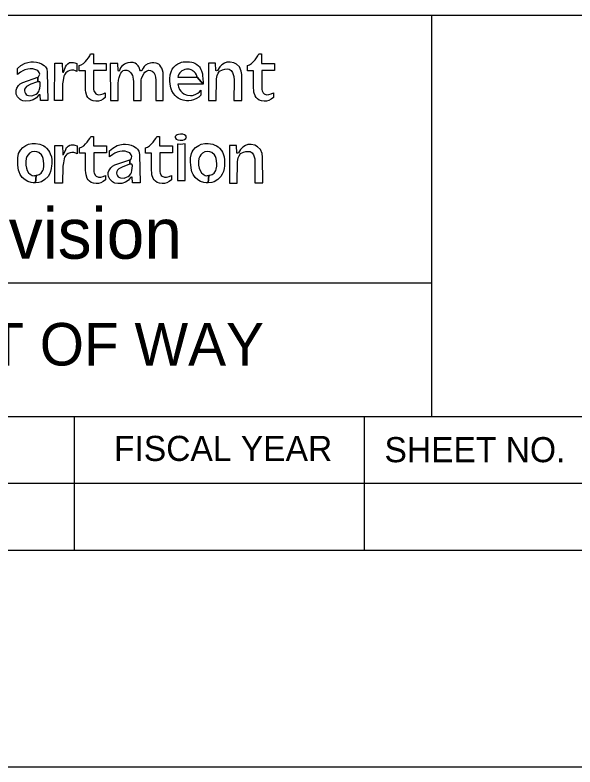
# Model space of a CAD drawing. Extents: x -507127 to -501139, y -509578 to -506434.
# Drawn here: x -504651.4 to -504486.7, y -508267.1 to -508046 of the extents above; entities that cross this region are included whole.
import ezdxf

# ---------------------------------------------------------------- set-up
doc = ezdxf.new("R2010")
doc.units = 0
doc.layers.add('rowdsnConstructCell', color=7, linetype='Continuous')

msp = doc.modelspace()

# ---------------------------------------------------------------- linework, layer by layer
at = {"layer": 'rowdsnConstructCell'}
for p, q in [((-504971.83, -508045.97), (-504397.68, -508045.97)), ((-504528.91, -508045.97), (-504528.91, -508164.08)), ((-504840.59, -508124.71), (-504528.91, -508124.71)), ((-507022.35, -508164.08), (-504397.68, -508164.08)), ((-505381.93, -508164.08), (-504397.68, -508164.08)), ((-504633.9, -508203.46), (-504633.9, -508164.09)), ((-504548.6, -508203.46), (-504548.6, -508164.09)), ((-504397.68, -508183.77), (-504794.66, -508183.77)), ((-504397.68, -508203.45), (-507022.35, -508203.45)), ((-507126.68, -508267.1), (-504293.35, -508267.1))]:
    msp.add_line(p, q, dxfattribs=at)
for points in [[(-504632.5, -508060.84), (-504631.89, -508060.59), (-504631.25, -508060.2), (-504630.69, -508059.66), (-504630.22, -508059.14), (-504629.78, -508058.53), (-504629.41, -508058.01), (-504629.14, -508057.42), (-504628.33, -508057.42), (-504628.33, -508060.18), (-504624.55, -508060.18), (-504624.55, -508062.3), (-504628.28, -508062.3), (-504628.27, -508067.9), (-504628.17, -508068.22), (-504627.79, -508068.89), (-504627.79, -508068.89), (-504627.58, -508069.12), (-504626.89, -508069.42), (-504626.22, -508069.39), (-504625.49, -508069.18), (-504624.82, -508068.89), (-504624.82, -508070.24), (-504625.47, -508070.69), (-504626.17, -508071.07), (-504626.87, -508071.26), (-504627.19, -508071.28), (-504627.59, -508071.29), (-504628.37, -508071.16), (-504629.01, -508070.97), (-504629.55, -508070.58), (-504629.93, -508070.21), (-504630.21, -508069.78), (-504630.56, -508068.69), (-504630.63, -508068.03), (-504630.68, -508067.49), (-504630.68, -508062.35), (-504632.5, -508062.35)], [(-504583.04, -508060.84), (-504582.43, -508060.59), (-504581.8, -508060.2), (-504581.24, -508059.66), (-504580.77, -508059.14), (-504580.33, -508058.53), (-504579.95, -508058.01), (-504579.69, -508057.42), (-504578.88, -508057.42), (-504578.88, -508060.18), (-504575.1, -508060.18), (-504575.1, -508062.3), (-504578.83, -508062.3), (-504578.81, -508067.9), (-504578.72, -508068.22), (-504578.35, -508068.89), (-504578.35, -508068.89), (-504578.13, -508069.12), (-504577.44, -508069.42), (-504576.77, -508069.39), (-504576.04, -508069.18), (-504575.37, -508068.89), (-504575.37, -508070.24), (-504576.02, -508070.69), (-504576.71, -508071.07), (-504577.41, -508071.26), (-504577.74, -508071.28), (-504578.14, -508071.29), (-504578.92, -508071.16), (-504579.56, -508070.97), (-504580.1, -508070.58), (-504580.48, -508070.21), (-504580.76, -508069.78), (-504581.11, -508068.69), (-504581.17, -508068.03), (-504581.23, -508067.49), (-504581.23, -508062.35), (-504583.04, -508062.35)], [(-504650.66, -508063.46), (-504650.66, -508061.72), (-504649.7, -508060.86), (-504648.41, -508060.14), (-504647.6, -508059.91), (-504646.71, -508059.74), (-504645.98, -508059.72), (-504645.06, -508059.86), (-504644.32, -508060.01), (-504643.6, -508060.29), (-504643.6, -508060.29), (-504642.84, -508060.77), (-504642.44, -508061.23), (-504642.06, -508061.79), (-504641.89, -508062.75), (-504641.68, -508071.13), (-504643.93, -508071.13), (-504644, -508069.45), (-504644.24, -508069.42), (-504644.46, -508069.54), (-504645.08, -508070.28), (-504645.52, -508070.59), (-504646, -508070.89), (-504647.01, -508071.24), (-504648.22, -508071.32), (-504649.08, -508071.19), (-504649.53, -508070.99), (-504649.84, -508070.8), (-504650.43, -508070.24), (-504650.61, -508070.02), (-504650.99, -508069.23), (-504651.06, -508068.61), (-504651.05, -508068.08), (-504650.84, -508067.52), (-504650.34, -508066.7), (-504649.83, -508066.22), (-504649.1, -508065.82), (-504644.7, -508064.29), (-504644.7, -508065.64), (-504645.03, -508065.71), (-504646.72, -508066.35), (-504647.98, -508066.99), (-504648.34, -508067.35), (-504648.55, -508067.8), (-504648.59, -508068.29), (-504648.5, -508068.66), (-504648.31, -508069.09), (-504648.09, -508069.3), (-504647.78, -508069.51), (-504647.43, -508069.64), (-504646.42, -508069.7), (-504645.64, -508069.46), (-504645.17, -508069.23), (-504644.78, -508068.92), (-504644.42, -508068.49), (-504644.25, -508068.1), (-504644.1, -508067.49), (-504643.99, -508066.79), (-504643.95, -508066.11), (-504643.98, -508065.77), (-504644.06, -508065.66), (-504644.17, -508065.58), (-504644.51, -508065.62), (-504644.7, -508065.64), (-504644.7, -508064.29), (-504644.45, -508064.18), (-504644.23, -508063.74), (-504644.12, -508063.35), (-504644.26, -508062.83), (-504644.69, -508062.3), (-504645.56, -508061.96), (-504646.1, -508061.81), (-504646.92, -508061.77), (-504647.61, -508061.89), (-504648.47, -508062.1), (-504649.08, -508062.4), (-504649.73, -508062.8)], [(-504639.7, -508060.12), (-504637.47, -508060.12), (-504637.42, -508062.68), (-504637.35, -508062.82), (-504637.15, -508062.77), (-504637.06, -508062.55), (-504636.54, -508061.25), (-504636.27, -508060.73), (-504636.06, -508060.48), (-504635.83, -508060.29), (-504635.33, -508059.97), (-504634.98, -508059.92), (-504634.61, -508059.92), (-504634.16, -508059.96), (-504633.81, -508060.05), (-504633.17, -508060.22), (-504633.17, -508062.57), (-504633.59, -508062.39), (-504634.1, -508062.2), (-504634.39, -508062.16), (-504634.72, -508062.17), (-504635.26, -508062.31), (-504635.79, -508062.5), (-504636.16, -508062.74), (-504636.44, -508063), (-504636.86, -508063.57), (-504637.01, -508063.99), (-504637.23, -508065.19), (-504637.37, -508066.2), (-504637.46, -508071.14), (-504639.72, -508071.14)], [(-504621.03, -508071.11), (-504621.03, -508066.1), (-504620.9, -508065.08), (-504620.73, -508064.39), (-504620.43, -508063.47), (-504620.26, -508063.07), (-504620.01, -508062.66), (-504619.55, -508062.33), (-504619.16, -508062.23), (-504618.48, -508062.19), (-504618.2, -508062.24), (-504617.8, -508062.5), (-504617.44, -508062.83), (-504617.44, -508062.83), (-504617.15, -508063.24), (-504616.86, -508063.71), (-504616.75, -508064.12), (-504616.75, -508064.12), (-504616.63, -508064.93), (-504616.57, -508065.42), (-504616.56, -508071.12), (-504614.3, -508071.13), (-504614.3, -508065.01), (-504614.21, -508064.63), (-504614.01, -508064.17), (-504613.44, -508063.09), (-504613.15, -508062.73), (-504612.73, -508062.44), (-504612.15, -508062.22), (-504611.53, -508062.28), (-504611.01, -508062.5), (-504611.01, -508062.5), (-504610.57, -508062.91), (-504610.27, -508063.44), (-504610.09, -508064.28), (-504610.01, -508065.17), (-504609.97, -508066.25), (-504609.93, -508071.14), (-504607.84, -508071.14), (-504607.84, -508062.91), (-504608, -508062.14), (-504608.23, -508061.59), (-504608.45, -508061.23), (-504608.78, -508060.76), (-504609.09, -508060.47), (-504609.85, -508060.16), (-504610.55, -508060.02), (-504611.16, -508060.06), (-504611.66, -508060.12), (-504612.32, -508060.31), (-504612.97, -508060.68), (-504613.37, -508061.06), (-504613.71, -508061.59), (-504614.09, -508062.25), (-504614.27, -508062.4), (-504614.47, -508062.37), (-504614.63, -508062.12), (-504614.74, -508061.58), (-504614.94, -508061.2), (-504615.19, -508060.89), (-504615.61, -508060.39), (-504616.07, -508060.14), (-504616.66, -508059.98), (-504617.43, -508059.89), (-504618.24, -508060.01), (-504618.78, -508060.22), (-504619.22, -508060.42), (-504620.07, -508061.15), (-504620.32, -508061.48), (-504620.55, -508061.95), (-504620.75, -508062.46), (-504620.97, -508062.46), (-504621.01, -508062.27), (-504621.15, -508060.18), (-504623.35, -508060.18), (-504623.34, -508071.11)], [(-504603.54, -508066.26), (-504603.34, -508067.12), (-504602.98, -508067.87), (-504602.62, -508068.34), (-504602.2, -508068.76), (-504601.71, -508069.11), (-504601.06, -508069.41), (-504600.61, -508069.55), (-504599.78, -508069.64), (-504599.19, -508069.59), (-504598.38, -508069.38), (-504597.65, -508068.99), (-504597.09, -508068.54), (-504596.72, -508068.11), (-504596.72, -508069.58), (-504597.31, -508070.1), (-504598, -508070.55), (-504598.84, -508070.93), (-504599.59, -508071.12), (-504600.28, -508071.2), (-504600.99, -508071.19), (-504601.96, -508071.01), (-504602.58, -508070.79), (-504603.37, -508070.38), (-504603.84, -508070.03), (-504604.3, -508069.61), (-504604.75, -508069.08), (-504605.25, -508068.26), (-504605.58, -508067.4), (-504605.77, -508066.35), (-504605.88, -508065.43), (-504605.87, -508064.73), (-504605.72, -508063.58), (-504605.47, -508062.69), (-504605.14, -508061.9), (-504604.65, -508061.27), (-504604.1, -508060.75), (-504603.48, -508060.32), (-504602.79, -508060), (-504602.43, -508059.88), (-504601.88, -508059.75), (-504601.12, -508059.7), (-504600.06, -508059.74), (-504599.33, -508059.85), (-504598.97, -508059.96), (-504598.51, -508060.15), (-504598.18, -508060.33), (-504597.87, -508060.54), (-504597.41, -508060.94), (-504597.16, -508061.23), (-504596.94, -508061.52), (-504596.69, -508061.95), (-504596.49, -508062.41), (-504596.28, -508063.27), (-504596.21, -508063.77), (-504596.12, -508064.76), (-504596.08, -508065.75), (-504596.08, -508066.26), (-504597.77, -508064.27), (-504598, -508063.56), (-504598.27, -508063.11), (-504598.69, -508062.64), (-504598.94, -508062.44), (-504599.2, -508062.28), (-504599.58, -508062.09), (-504600.19, -508061.93), (-504600.92, -508061.9), (-504601.44, -508062), (-504601.83, -508062.14), (-504602.29, -508062.39), (-504602.91, -508062.95), (-504603.21, -508063.38), (-504603.43, -508063.85), (-504603.54, -508064.27), (-504597.77, -508064.27), (-504596.08, -508066.26)], [(-504594.49, -508071.14), (-504592.2, -508071.14), (-504592.16, -508064.77), (-504591.94, -508063.75), (-504591.66, -508063.11), (-504591.26, -508062.51), (-504590.39, -508062.07), (-504589.68, -508061.89), (-504589, -508061.84), (-504588.42, -508061.91), (-504587.81, -508062.26), (-504587.42, -508062.84), (-504587.19, -508063.47), (-504587.06, -508064.03), (-504586.97, -508065.15), (-504586.99, -508071.12), (-504584.7, -508071.12), (-504584.72, -508063.5), (-504584.86, -508062.44), (-504584.86, -508062.44), (-504585.38, -508061.25), (-504586.21, -508060.47), (-504586.21, -508060.47), (-504587.04, -508060.02), (-504587.04, -508060.02), (-504588.13, -508059.81), (-504589.05, -508059.86), (-504589.73, -508060.1), (-504590.55, -508060.63), (-504591.19, -508061.25), (-504591.19, -508061.25), (-504591.87, -508062.28), (-504592.08, -508062.4), (-504592.31, -508062.32), (-504592.4, -508060.17), (-504594.49, -508060.17)], [(-504632.43, -508085.07), (-504631.83, -508084.81), (-504631.18, -508084.43), (-504630.63, -508083.88), (-504630.16, -508083.37), (-504629.72, -508082.76), (-504629.35, -508082.24), (-504629.08, -508081.65), (-504628.27, -508081.65), (-504628.27, -508084.41), (-504624.49, -508084.41), (-504624.49, -508086.53), (-504628.22, -508086.53), (-504628.21, -508092.13), (-504628.11, -508092.45), (-504627.73, -508093.12), (-504627.73, -508093.12), (-504627.52, -508093.35), (-504626.83, -508093.65), (-504626.16, -508093.62), (-504625.43, -508093.41), (-504624.76, -508093.12), (-504624.76, -508094.47), (-504625.41, -508094.92), (-504626.11, -508095.3), (-504626.81, -508095.49), (-504627.13, -508095.51), (-504627.53, -508095.52), (-504628.31, -508095.39), (-504628.95, -508095.2), (-504629.49, -508094.8), (-504629.87, -508094.43), (-504630.15, -508094), (-504630.5, -508092.92), (-504630.56, -508092.26), (-504630.62, -508091.72), (-504630.62, -508086.58), (-504632.43, -508086.58)], [(-504613.05, -508085.07), (-504612.44, -508084.81), (-504611.8, -508084.43), (-504611.25, -508083.88), (-504610.78, -508083.37), (-504610.34, -508082.76), (-504609.96, -508082.24), (-504609.7, -508081.65), (-504608.89, -508081.65), (-504608.89, -508084.41), (-504605.11, -508084.41), (-504605.11, -508086.53), (-504608.83, -508086.53), (-504608.82, -508092.13), (-504608.73, -508092.45), (-504608.35, -508093.12), (-504608.35, -508093.12), (-504608.14, -508093.35), (-504607.45, -508093.65), (-504606.78, -508093.62), (-504606.05, -508093.41), (-504605.38, -508093.12), (-504605.38, -508094.47), (-504606.03, -508094.92), (-504606.72, -508095.3), (-504607.42, -508095.49), (-504607.75, -508095.51), (-504608.15, -508095.52), (-504608.93, -508095.39), (-504609.56, -508095.2), (-504610.11, -508094.8), (-504610.49, -508094.43), (-504610.77, -508094), (-504611.12, -508092.92), (-504611.18, -508092.26), (-504611.24, -508091.72), (-504611.24, -508086.58), (-504613.05, -508086.58)], [(-504604.32, -508081.97), (-504604.03, -508082.45), (-504603.52, -508082.69), (-504602.76, -508082.81), (-504602.76, -508082.81), (-504602.06, -508082.74), (-504601.52, -508082.57), (-504601.11, -508082.26), (-504601.02, -508082.01), (-504600.98, -508081.83), (-504601.15, -508081.48), (-504601.55, -508081.2), (-504602.04, -508081.05), (-504602.04, -508081.05), (-504602.71, -508080.96), (-504603.34, -508081.06), (-504603.7, -508081.21), (-504604.03, -508081.39), (-504604.23, -508081.66)], [(-504646.36, -508083.77), (-504645.38, -508083.78), (-504644.05, -508083.97), (-504643.6, -508084.16), (-504642.94, -508084.41), (-504642.48, -508084.75), (-504642.12, -508085.09), (-504641.53, -508085.77), (-504641.19, -508086.3), (-504641, -508086.76), (-504640.67, -508087.67), (-504640.59, -508088.54), (-504640.57, -508089.72), (-504640.6, -508090.34), (-504640.71, -508091.08), (-504640.94, -508092), (-504641.28, -508092.8), (-504641.66, -508093.45), (-504642.57, -508094.36), (-504642.59, -508094.38), (-504643.59, -508094.98), (-504644.33, -508095.22), (-504645.4, -508095.32), (-504645.16, -508093.19), (-504644.25, -508092.91), (-504643.65, -508092.49), (-504643.18, -508091.72), (-504643, -508091.26), (-504642.9, -508090.44), (-504642.88, -508089.64), (-504643.08, -508088.18), (-504643.28, -508087.59), (-504643.56, -508087.12), (-504644.34, -508086.43), (-504644.96, -508086.16), (-504645.65, -508086.1), (-504646.44, -508086.22), (-504647.09, -508086.61), (-504647.55, -508087.06), (-504647.86, -508087.54), (-504648.1, -508088.19), (-504648.21, -508089.08), (-504648.21, -508090.12), (-504648.02, -508091.05), (-504647.79, -508091.68), (-504647.42, -508092.37), (-504646.89, -508092.82), (-504646.29, -508093.12), (-504645.79, -508093.22), (-504645.59, -508093.21), (-504645.07, -508093.19), (-504645.16, -508093.19), (-504645.4, -508095.32), (-504646.04, -508095.33), (-504646.64, -508095.22), (-504647.65, -508094.94), (-504648.43, -508094.43), (-504649.26, -508093.71), (-504649.85, -508092.84), (-504650.18, -508092.08), (-504650.35, -508091.57), (-504650.53, -508090.08), (-504650.59, -508089.13), (-504650.59, -508087.97), (-504650.32, -508086.72), (-504650.08, -508086.24), (-504649.8, -508085.67), (-504649.09, -508084.91), (-504648.19, -508084.3), (-504647.46, -508083.98)], [(-504639.63, -508084.35), (-504637.41, -508084.35), (-504637.36, -508086.91), (-504637.28, -508087.05), (-504637.08, -508086.99), (-504636.99, -508086.78), (-504636.47, -508085.47), (-504636.2, -508084.96), (-504635.99, -508084.7), (-504635.76, -508084.51), (-504635.26, -508084.2), (-504634.91, -508084.15), (-504634.54, -508084.15), (-504634.09, -508084.19), (-504633.74, -508084.28), (-504633.1, -508084.45), (-504633.1, -508086.8), (-504633.52, -508086.62), (-504634.04, -508086.43), (-504634.33, -508086.39), (-504634.64, -508086.4), (-504635.19, -508086.54), (-504635.72, -508086.73), (-504636.09, -508086.97), (-504636.37, -508087.23), (-504636.79, -508087.8), (-504636.94, -508088.22), (-504637.16, -508089.42), (-504637.3, -508090.43), (-504637.39, -508095.37), (-504639.66, -508095.37)], [(-504623.57, -508087.69), (-504623.57, -508085.95), (-504622.6, -508085.09), (-504621.32, -508084.37), (-504620.51, -508084.14), (-504619.61, -508083.96), (-504618.88, -508083.95), (-504617.96, -508084.08), (-504617.23, -508084.24), (-504616.5, -508084.52), (-504616.5, -508084.52), (-504615.75, -508085), (-504615.34, -508085.46), (-504614.97, -508086.02), (-504614.79, -508086.98), (-504614.58, -508095.36), (-504616.84, -508095.36), (-504616.91, -508093.68), (-504617.15, -508093.65), (-504617.37, -508093.76), (-504617.99, -508094.51), (-504618.43, -508094.82), (-504618.9, -508095.12), (-504619.92, -508095.47), (-504621.13, -508095.54), (-504621.98, -508095.42), (-504622.43, -508095.21), (-504622.75, -508095.03), (-504623.33, -508094.47), (-504623.52, -508094.25), (-504623.89, -508093.46), (-504623.97, -508092.84), (-504623.95, -508092.31), (-504623.75, -508091.76), (-504623.24, -508090.93), (-504622.74, -508090.45), (-504622.01, -508090.05), (-504617.6, -508088.52), (-504617.6, -508089.87), (-504617.94, -508089.94), (-504619.62, -508090.58), (-504620.89, -508091.22), (-504621.24, -508091.58), (-504621.45, -508092.03), (-504621.5, -508092.51), (-504621.4, -508092.89), (-504621.21, -508093.31), (-504621, -508093.53), (-504620.69, -508093.74), (-504620.33, -508093.87), (-504619.32, -508093.93), (-504618.55, -508093.69), (-504618.08, -508093.45), (-504617.69, -508093.15), (-504617.33, -508092.72), (-504617.16, -508092.33), (-504617, -508091.72), (-504616.89, -508091.02), (-504616.86, -508090.34), (-504616.89, -508090), (-504616.97, -508089.89), (-504617.07, -508089.81), (-504617.41, -508089.84), (-504617.6, -508089.87), (-504617.6, -508088.52), (-504617.35, -508088.41), (-504617.14, -508087.97), (-504617.02, -508087.58), (-504617.17, -508087.05), (-504617.6, -508086.52), (-504618.47, -508086.19), (-504619, -508086.04), (-504619.82, -508086), (-504620.51, -508086.12), (-504621.38, -508086.33), (-504621.99, -508086.62), (-504622.64, -508087.03)], [(-504603.63, -508083.95), (-504603.63, -508094.61), (-504601.3, -508094.61), (-504601.3, -508083.84), (-504601.98, -508083.96), (-504601.98, -508083.96), (-504602.8, -508084.02), (-504602.8, -508084.02), (-504603.41, -508083.98)], [(-504595.52, -508083.77), (-504594.54, -508083.78), (-504593.22, -508083.97), (-504592.77, -508084.16), (-504592.11, -508084.41), (-504591.65, -508084.75), (-504591.28, -508085.09), (-504590.7, -508085.77), (-504590.36, -508086.3), (-504590.16, -508086.76), (-504589.84, -508087.67), (-504589.76, -508088.54), (-504589.73, -508089.72), (-504589.77, -508090.34), (-504589.87, -508091.08), (-504590.11, -508092), (-504590.45, -508092.8), (-504590.82, -508093.45), (-504591.73, -508094.36), (-504591.76, -508094.38), (-504592.76, -508094.98), (-504593.5, -508095.22), (-504594.57, -508095.32), (-504594.33, -508093.19), (-504593.41, -508092.91), (-504592.82, -508092.49), (-504592.35, -508091.72), (-504592.18, -508091.26), (-504592.06, -508090.44), (-504592.04, -508089.64), (-504592.25, -508088.18), (-504592.45, -508087.59), (-504592.73, -508087.12), (-504593.51, -508086.43), (-504594.13, -508086.16), (-504594.82, -508086.1), (-504595.6, -508086.22), (-504596.25, -508086.61), (-504596.72, -508087.06), (-504597.03, -508087.54), (-504597.27, -508088.19), (-504597.37, -508089.08), (-504597.38, -508090.12), (-504597.19, -508091.05), (-504596.96, -508091.68), (-504596.58, -508092.37), (-504596.06, -508092.82), (-504595.46, -508093.12), (-504594.96, -508093.22), (-504594.76, -508093.21), (-504594.24, -508093.19), (-504594.33, -508093.19), (-504594.57, -508095.32), (-504595.2, -508095.33), (-504595.81, -508095.22), (-504596.82, -508094.94), (-504597.6, -508094.43), (-504598.43, -508093.71), (-504599.02, -508092.84), (-504599.35, -508092.08), (-504599.51, -508091.57), (-504599.7, -508090.08), (-504599.76, -508089.13), (-504599.76, -508087.97), (-504599.48, -508086.72), (-504599.24, -508086.24), (-504598.96, -508085.67), (-504598.26, -508084.91), (-504597.36, -508084.3), (-504596.63, -508083.98)], [(-504588.31, -508095.37), (-504586.03, -508095.37), (-504585.99, -508089), (-504585.76, -508087.97), (-504585.49, -508087.34), (-504585.08, -508086.74), (-504584.21, -508086.3), (-504583.51, -508086.12), (-504582.83, -508086.07), (-504582.25, -508086.14), (-504581.63, -508086.49), (-504581.24, -508087.07), (-504581.02, -508087.7), (-504580.89, -508088.26), (-504580.8, -508089.38), (-504580.81, -508095.35), (-504578.53, -508095.35), (-504578.55, -508087.73), (-504578.68, -508086.67), (-504578.68, -508086.67), (-504579.2, -508085.48), (-504580.03, -508084.7), (-504580.03, -508084.7), (-504580.86, -508084.25), (-504580.86, -508084.25), (-504581.95, -508084.04), (-504582.87, -508084.08), (-504583.55, -508084.33), (-504584.38, -508084.87), (-504585.02, -508085.48), (-504585.02, -508085.48), (-504585.69, -508086.51), (-504585.9, -508086.63), (-504586.13, -508086.55), (-504586.23, -508084.39), (-504588.31, -508084.39)]]:
    msp.add_lwpolyline(points, close=True, dxfattribs=at)

# ---------------------------------------------------------------- texts
for s, height, p in [('Higway Division', 14.8983, (-504742.87, -508117.64)), ('OFFICE OF RIGHT OF WAY', 12.5, (-504794.52, -508149.04)), ('FISCAL YEAR', 7.3819, (-504622.27, -508177.11)), ('SHEET NO.', 7.382, (-504542.72, -508177.48))]:
    msp.add_text(s, height=height, dxfattribs=at).set_placement(p)

doc.saveas('drawing.dxf')
